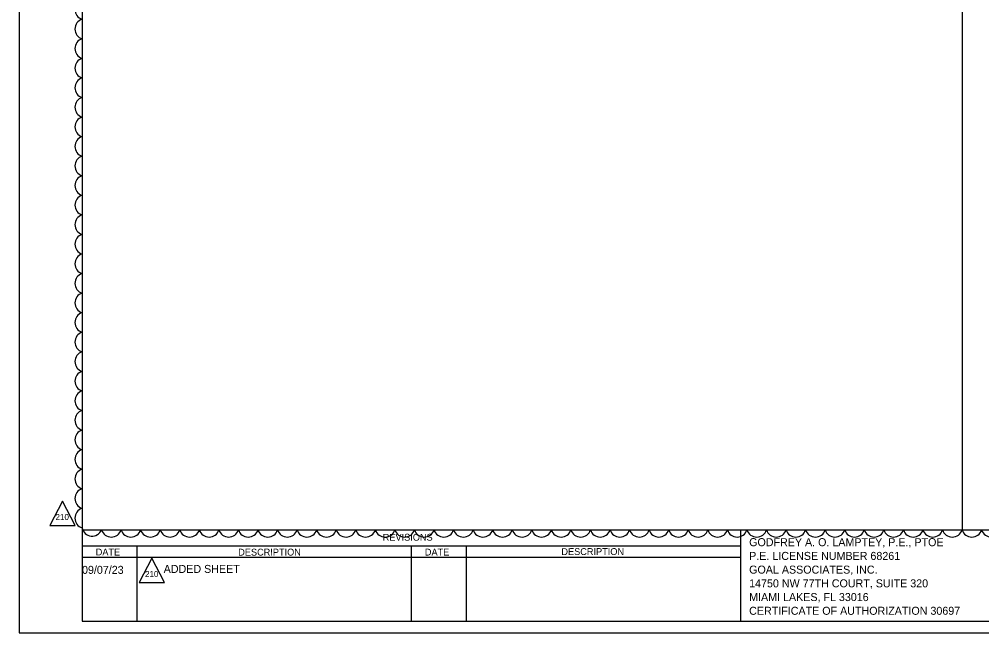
# Model space of a CAD drawing. Extents: x -811.3 to -790.1, y -2211.9 to -2188.9.
# Drawn here: x -811.34 to -802.91, y -2211.94 to -2206.57 of the extents above; entities that cross this region are included whole.
import ezdxf

# ---------------------------------------------------------------- set-up
doc = ezdxf.new("R2010")
doc.units = 0
for name, color, linetype in [('AdhocPoint_dp', 7, 'Continuous'), ('Cloud_dp', 7, 'Continuous'), ('PlotBorder_dp', 7, 'Continuous'), ('SheetBorder_dp', 7, 'Continuous'), ('SheetLines_dp', 7, 'Continuous'), ('TextLabel', 7, 'Continuous'), ('TextMisc', 7, 'Continuous'), ('TextTitle', 7, 'Continuous')]:
    doc.layers.add(name, color=color, linetype=linetype)

msp = doc.modelspace()

# ---------------------------------------------------------------- linework, layer by layer
at = {"layer": 'AdhocPoint_dp'}
msp.add_line((-811.3358, -2211.9401), (-811.3358, -2211.9401), dxfattribs=at)
msp.add_line((-811.3358, -2211.9401), (-811.3358, -2211.9401), dxfattribs=at)
at = {"layer": 'Cloud_dp'}
for points in [[(-810.9581, -2210.7887), (-811.069, -2211.0023), (-810.8472, -2211.0023)], [(-810.1749, -2211.2872), (-810.2858, -2211.5008), (-810.064, -2211.5008)]]:
    msp.add_lwpolyline(points, close=True, dxfattribs=at)
for centre, radius, start, end in [((-810.7588, -2206.4882), 0.0897, 107.5, 252.5), ((-810.7588, -2206.6593), 0.0897, 107.5, 252.5), ((-810.7588, -2206.8304), 0.0897, 107.5, 252.5), ((-810.7588, -2207.0015), 0.0897, 107.5, 252.5), ((-810.7588, -2207.1727), 0.0897, 107.5, 252.5), ((-810.7588, -2207.3438), 0.0897, 107.5, 252.5), ((-810.7588, -2207.5149), 0.0897, 107.5, 252.5), ((-810.7588, -2207.686), 0.0897, 107.5, 252.5), ((-810.7588, -2207.8571), 0.0897, 107.5, 252.5), ((-810.7588, -2208.0283), 0.0897, 107.5, 252.5), ((-810.7588, -2208.1994), 0.0897, 107.5, 252.5), ((-810.7588, -2208.3705), 0.0897, 107.5, 252.5), ((-810.7588, -2208.5416), 0.0897, 107.5, 252.5), ((-810.7588, -2208.7128), 0.0897, 107.5, 252.5), ((-810.7588, -2208.8839), 0.0897, 107.5, 252.5), ((-810.7588, -2209.055), 0.0897, 107.5, 252.5), ((-810.7588, -2209.2261), 0.0897, 107.5, 252.5), ((-810.7588, -2209.3972), 0.0897, 107.5, 252.5), ((-810.7588, -2209.5684), 0.0897, 107.5, 252.5), ((-810.7588, -2209.7395), 0.0897, 107.5, 252.5), ((-810.7588, -2209.9106), 0.0897, 107.5, 252.5), ((-810.7588, -2210.0817), 0.0897, 107.5, 252.5), ((-810.7588, -2210.2529), 0.0897, 107.5, 252.5), ((-810.7588, -2210.424), 0.0897, 107.5, 252.5), ((-810.7588, -2210.5951), 0.0897, 107.5, 252.5), ((-810.7588, -2210.7662), 0.0897, 107.5, 252.5), ((-810.7588, -2210.9373), 0.0897, 107.5, 252.5), ((-810.698, -2211.0047), 0.0896, 191.74536, 336.74536), ((-810.5301, -2211.0131), 0.0897, 197.5, 342.5), ((-810.359, -2211.0131), 0.0897, 197.5, 342.5), ((-810.1879, -2211.0131), 0.0897, 197.5, 342.5), ((-810.0167, -2211.0131), 0.0897, 197.5, 342.5), ((-809.8456, -2211.0131), 0.0897, 197.5, 342.5), ((-809.6745, -2211.0131), 0.0897, 197.5, 342.5), ((-809.5034, -2211.0131), 0.0897, 197.5, 342.5), ((-809.3323, -2211.0131), 0.0897, 197.5, 342.5), ((-809.1611, -2211.0131), 0.0897, 197.5, 342.5), ((-808.99, -2211.0131), 0.0897, 197.5, 342.5), ((-808.8189, -2211.0131), 0.0897, 197.5, 342.5), ((-808.6478, -2211.0131), 0.0897, 197.5, 342.5), ((-808.4766, -2211.0131), 0.0897, 197.5, 342.5), ((-808.3055, -2211.0131), 0.0897, 197.5, 342.5), ((-808.1344, -2211.0131), 0.0897, 197.5, 342.5), ((-807.9633, -2211.0131), 0.0897, 197.5, 342.5), ((-807.7921, -2211.0131), 0.0897, 197.5, 342.5), ((-807.621, -2211.0131), 0.0897, 197.5, 342.5), ((-807.4499, -2211.0131), 0.0897, 197.5, 342.5), ((-807.2788, -2211.0131), 0.0897, 197.5, 342.5), ((-807.1077, -2211.0131), 0.0897, 197.5, 342.5), ((-806.9365, -2211.0131), 0.0897, 197.5, 342.5), ((-806.7654, -2211.0131), 0.0897, 197.5, 342.5), ((-806.5943, -2211.0131), 0.0897, 197.5, 342.5), ((-806.4232, -2211.0131), 0.0897, 197.5, 342.5), ((-806.252, -2211.0131), 0.0897, 197.5, 342.5), ((-806.0809, -2211.0131), 0.0897, 197.5, 342.5), ((-805.9098, -2211.0131), 0.0897, 197.5, 342.5), ((-805.7387, -2211.0131), 0.0897, 197.5, 342.5), ((-805.5676, -2211.0131), 0.0897, 197.5, 342.5), ((-805.3964, -2211.0131), 0.0897, 197.5, 342.5), ((-805.2253, -2211.0131), 0.0897, 197.5, 342.5), ((-805.0542, -2211.0131), 0.0897, 197.5, 342.5), ((-804.8831, -2211.0131), 0.0897, 197.5, 342.5), ((-804.7119, -2211.0131), 0.0897, 197.5, 342.5), ((-804.5408, -2211.0131), 0.0897, 197.5, 342.5), ((-804.3697, -2211.0131), 0.0897, 197.5, 342.5), ((-804.1986, -2211.0131), 0.0897, 197.5, 342.5), ((-804.0275, -2211.0131), 0.0897, 197.5, 342.5), ((-803.8563, -2211.0131), 0.0897, 197.5, 342.5), ((-803.6852, -2211.0131), 0.0897, 197.5, 342.5), ((-803.5141, -2211.0131), 0.0897, 197.5, 342.5), ((-803.343, -2211.0131), 0.0897, 197.5, 342.5), ((-803.1718, -2211.0131), 0.0897, 197.5, 342.5), ((-803.0007, -2211.0131), 0.0897, 197.5, 342.5), ((-802.8296, -2211.0131), 0.0897, 197.5, 342.5)]:
    msp.add_arc(centre, radius, start, end, dxfattribs=at)
at = {"layer": 'PlotBorder_dp'}
msp.add_lwpolyline([(-811.3358, -2211.9401), (-794.8358, -2211.9401), (-794.8358, -2201.3401), (-811.3358, -2201.3401)], close=True, dxfattribs=at)
at = {"layer": 'SheetBorder_dp'}
for p, q in [((-810.7858, -2201.4401), (-810.7858, -2211.8401)), ((-803.0858, -2201.4401), (-803.0858, -2211.0401)), ((-810.7858, -2211.0401), (-795.3858, -2211.0401)), ((-810.7858, -2211.8401), (-795.3858, -2211.8401))]:
    msp.add_line(p, q, dxfattribs=at)
at = {"layer": 'SheetLines_dp'}
for p, q in [((-805.0258, -2211.0401), (-805.0258, -2211.8401)), ((-810.7858, -2211.1801), (-805.0258, -2211.1801)), ((-810.3058, -2211.1801), (-810.3058, -2211.8401)), ((-807.9058, -2211.1801), (-807.9058, -2211.8401)), ((-807.4258, -2211.1801), (-807.4258, -2211.8401)), ((-810.7858, -2211.2801), (-805.0258, -2211.2801))]:
    msp.add_line(p, q, dxfattribs=at)

# ---------------------------------------------------------------- texts
at = {"layer": 'Cloud_dp'}
for p in [(-811.0184, -2210.9541), (-810.2353, -2211.4527)]:
    msp.add_text('210', height=0.0525, rotation=360, dxfattribs=at).set_placement(p)
at = {"layer": 'TextLabel'}
for s, p in [('09/07/23', (-810.7867, -2211.4249)), ('ADDED SHEET', (-810.0721, -2211.4168))]:
    msp.add_text(s, height=0.07, rotation=0, dxfattribs=at).set_placement(p)
at = {"layer": 'TextMisc'}
msp.add_text('REVISIONS', height=0.06, dxfattribs=at).set_placement((-808.1553, -2211.1349))
for s, rotation, p in [('DATE', 359.86925, (-810.6668, -2211.2641)), ('DESCRIPTION', 0.04975, (-809.4198, -2211.2653)), ('DATE', 359.86925, (-807.7868, -2211.2647)), ('DESCRIPTION', 0.04975, (-806.5922, -2211.2603))]:
    msp.add_text(s, height=0.06, rotation=rotation, dxfattribs=at).set_placement(p)
at = {"layer": 'TextTitle'}
for s, p in [('GODFREY A. O. LAMPTEY, P.E., PTOE', (-804.9493, -2211.1829)), ('P.E. LICENSE NUMBER 68261', (-804.9493, -2211.3029)), ('GOAL ASSOCIATES, INC.', (-804.9493, -2211.4229)), ('14750 NW 77TH COURT, SUITE 320', (-804.9493, -2211.5429)), ('MIAMI LAKES, FL 33016', (-804.9493, -2211.6629)), ('CERTIFICATE OF AUTHORIZATION 30697', (-804.9493, -2211.7829))]:
    msp.add_text(s, height=0.07, dxfattribs=at).set_placement(p)

doc.saveas('drawing.dxf')
